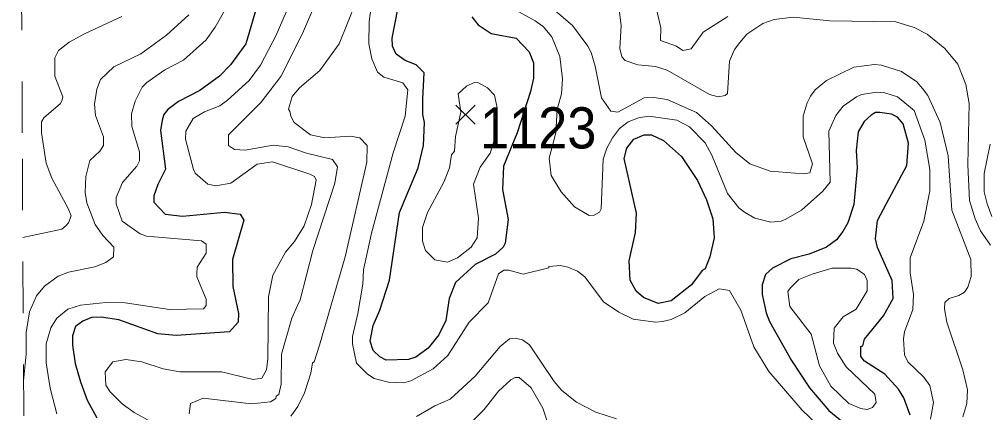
# Model space of a CAD drawing. Extents: x 423 to 448.8, y 7456.3 to 7484.
# Drawn here: x 423.019 to 424.902, y 7477.17 to 7477.935 of the extents above; entities that cross this region are included whole.
import ezdxf
from ezdxf.enums import TextEntityAlignment as Align

# ---------------------------------------------------------------- set-up
doc = ezdxf.new("R2010")
doc.units = 0
doc.header["$LTSCALE"] = 0.032
doc.linetypes.add('SHORT_DASHED', pattern=[2.7, 1.5, -1.2])
for name, color, linetype, lineweight in [('1', 7, 'Continuous', 25), ('2', 7, 'Continuous', 13), ('21', 7, 'Continuous', 25), ('22', 7, 'SHORT_DASHED', 13)]:
    doc.layers.add(name, color=color, linetype=linetype, lineweight=lineweight)
doc.layers.add('61', color=7, linetype='Continuous')

msp = doc.modelspace()

# ---------------------------------------------------------------- linework, layer by layer
at = {"layer": '1'}
for points in [[(423.4827, 7477.9691), (423.4587, 7477.8872), (423.4293, 7477.8461), (423.4076, 7477.8245), (423.3698, 7477.7966), (423.328, 7477.775), (423.3078, 7477.7595), (423.2994, 7477.7495), (423.2963, 7477.7387), (423.2932, 7477.7185), (423.3032, 7477.6435), (423.2878, 7477.6134), (423.28, 7477.5917), (423.28, 7477.5793), (423.3025, 7477.5561), (423.3357, 7477.5522), (423.4177, 7477.5599), (423.4479, 7477.5561), (423.4548, 7477.5445), (423.4332, 7477.4679), (423.4339, 7477.4153), (423.4448, 7477.3628), (423.444, 7477.3457), (423.427, 7477.3271), (423.3234, 7477.3202), (423.2878, 7477.3233), (423.212, 7477.3504), (423.1779, 7477.3558), (423.1594, 7477.355), (423.1424, 7477.348), (423.1284, 7477.3372), (423.1222, 7477.3194), (423.1222, 7477.3009), (423.1277, 7477.2653), (423.1377, 7477.2297), (423.1509, 7477.1941), (423.1694, 7477.1601)], [(423.898, 7477.9398), (423.9104, 7477.9243), (423.9359, 7477.9073), (423.9839, 7477.898), (424.0094, 7477.8717), (424.0179, 7477.85), (424.0179, 7477.8206), (424.0117, 7477.7943), (423.9863, 7477.7139), (423.9594, 7477.6494), (423.9576, 7477.6041), (423.9684, 7477.5453), (423.963, 7477.4996), (423.9591, 7477.4919), (423.9437, 7477.478), (423.9042, 7477.4579), (423.8663, 7477.423), (423.8539, 7477.3921), (423.8478, 7477.3488), (423.8338, 7477.321), (423.8129, 7477.2954), (423.789, 7477.2777), (423.7751, 7477.273), (423.7317, 7477.2722), (423.7193, 7477.2784), (423.7062, 7477.2908), (423.7008, 7477.3086), (423.7062, 7477.3395), (423.7194, 7477.3689), (423.7379, 7477.4277), (423.7572, 7477.5592), (423.7936, 7477.6458), (423.8044, 7477.6892), (423.806, 7477.734), (423.8029, 7477.7495), (423.8029, 7477.7804), (423.8052, 7477.8307), (423.7897, 7477.8461), (423.7688, 7477.8547), (423.751, 7477.867), (423.7441, 7477.8825), (423.7433, 7477.898), (423.7545, 7477.9544)], [(424.7496, 7477.1647), (424.7372, 7477.1988), (424.7272, 7477.2158), (424.7001, 7477.2444), (424.6606, 7477.2699), (424.6537, 7477.2792), (424.6537, 7477.2985), (424.6575, 7477.3001), (424.6607, 7477.3125), (424.6978, 7477.3581), (424.7163, 7477.3921), (424.7148, 7477.4269), (424.6862, 7477.4911), (424.6823, 7477.5082), (424.6862, 7477.5437), (424.7039, 7477.5769), (424.7434, 7477.6505), (424.7465, 7477.6938), (424.7357, 7477.7317), (424.7249, 7477.7448), (424.7132, 7477.7502), (424.6908, 7477.7533), (424.6823, 7477.7533), (424.6738, 7477.7487), (424.6599, 7477.7363), (424.6483, 7477.7162), (424.6444, 7477.6799), (424.6467, 7477.6458), (424.6398, 7477.5747), (424.6282, 7477.5391), (424.6189, 7477.5221), (424.6065, 7477.5058), (424.5872, 7477.4919), (424.5532, 7477.478), (424.5176, 7477.4687), (424.482, 7477.4509), (424.4688, 7477.4385), (424.4619, 7477.4184), (424.4619, 7477.3999), (424.4696, 7477.3643), (424.4765, 7477.3473), (424.5191, 7477.2715), (424.5539, 7477.2181), (424.5918, 7477.174), (424.6305, 7477.1423)]]:
    msp.add_lwpolyline(points, dxfattribs=at)
msp.add_lwpolyline([(424.1942, 7477.6644), (424.1989, 7477.6845), (424.2128, 7477.7015), (424.2329, 7477.71), (424.2468, 7477.71), (424.2701, 7477.6992), (424.3056, 7477.6682), (424.3366, 7477.6211), (424.3536, 7477.584), (424.366, 7477.5468), (424.3691, 7477.5097), (424.3606, 7477.4726), (424.3513, 7477.4494), (424.3458, 7477.4463), (424.3249, 7477.4184), (424.2855, 7477.3875), (424.26, 7477.382), (424.2314, 7477.3937), (424.2174, 7477.4061), (424.2059, 7477.4277), (424.2035, 7477.4648), (424.2159, 7477.5205), (424.2182, 7477.5577)], close=True, dxfattribs=at)
at = {"layer": '2'}
for points in [[(423.2189, 7477.5421), (423.2073, 7477.5762), (423.2073, 7477.5886), (423.2197, 7477.6172), (423.2475, 7477.6489), (423.2522, 7477.6598), (423.2522, 7477.6768), (423.2375, 7477.7263), (423.2367, 7477.751), (423.2437, 7477.7758), (423.2576, 7477.8028), (423.2669, 7477.8121), (423.3017, 7477.8368), (423.338, 7477.8554), (423.3821, 7477.8949), (423.3992, 7477.9196), (423.4502, 7478.0093)], [(423.5948, 7477.9676), (423.5693, 7477.9073), (423.5267, 7477.8237), (423.4889, 7477.7734), (423.4254, 7477.71), (423.4254, 7477.6892), (423.437, 7477.6814), (423.4579, 7477.6806), (423.5121, 7477.6899), (423.5415, 7477.6868), (423.5771, 7477.6744), (423.6273, 7477.662), (423.6374, 7477.6481), (423.632, 7477.6164), (423.5894, 7477.485), (423.5646, 7477.389), (423.5592, 7477.3782), (423.5484, 7477.3535), (423.5283, 7477.2839), (423.5275, 7477.2251), (423.5229, 7477.205), (423.5182, 7477.2019), (423.5175, 7477.1972), (423.5066, 7477.191), (423.4703, 7477.1872), (423.376, 7477.198), (423.3512, 7477.1879), (423.3488, 7477.1678)], [(423.673, 7477.9676), (423.6405, 7477.8872), (423.6025, 7477.8353), (423.5631, 7477.8013)], [(424.5841, 7477.1323), (424.54, 7477.1748), (424.475, 7477.2498), (424.4456, 7477.2978), (424.4209, 7477.3689), (424.3985, 7477.4076), (424.3784, 7477.4107), (424.3505, 7477.396), (424.3118, 7477.3643), (424.2855, 7477.3511), (424.2685, 7477.3473), (424.2546, 7477.3457), (424.2113, 7477.3519), (424.1834, 7477.365), (424.154, 7477.3852), (424.1177, 7477.4339), (424.103, 7477.4447), (424.0844, 7477.4525), (424.0705, 7477.4563), (424.0473, 7477.454), (424.0473, 7477.4517), (423.9978, 7477.4393), (423.97, 7477.447), (423.9599, 7477.447), (423.9499, 7477.44), (423.9297, 7477.3836), (423.8926, 7477.3457), (423.8516, 7477.2808), (423.823, 7477.2552), (423.7797, 7477.232), (423.7658, 7477.2281), (423.7364, 7477.2289), (423.7085, 7477.2366), (423.6954, 7477.2444), (423.6737, 7477.266), (423.666, 7477.304), (423.666, 7477.3179), (423.6768, 7477.3628), (423.6861, 7477.42), (423.6876, 7477.4478), (423.7031, 7477.519), (423.7449, 7477.6752), (423.7688, 7477.7464), (423.7735, 7477.7974), (423.7642, 7477.8114), (423.7271, 7477.8221), (423.7147, 7477.8322), (423.7039, 7477.8578), (423.6977, 7477.8872), (423.6985, 7477.9305), (423.7046, 7477.9738)], [(423.9506, 7477.9707), (424.021, 7477.932), (424.0365, 7477.9211), (424.0535, 7477.901), (424.069, 7477.8624), (424.0744, 7477.8191), (424.0721, 7477.7897), (424.0635, 7477.7595), (424.0613, 7477.7141), (424.0485, 7477.665), (424.052, 7477.6311), (424.0713, 7477.5994), (424.0976, 7477.57)], [(424.8517, 7477.1617), (424.8594, 7477.1879), (424.861, 7477.2142), (424.8517, 7477.2529), (424.8207, 7477.3457), (424.8161, 7477.372), (424.8169, 7477.3844), (424.8254, 7477.3921), (424.844, 7477.3975), (424.8548, 7477.4045), (424.8617, 7477.4138), (424.8679, 7477.4347), (424.8672, 7477.4679), (424.8308, 7477.5639), (424.8231, 7477.669), (424.8076, 7477.734), (424.7836, 7477.7866), (424.7736, 7477.8005), (424.7628, 7477.8129), (424.7326, 7477.833), (424.6939, 7477.8454), (424.68, 7477.8469), (424.6398, 7477.8415), (424.5872, 7477.816), (424.5647, 7477.7974), (424.5562, 7477.7851), (424.5493, 7477.7727), (424.5415, 7477.7464), (424.5415, 7477.7062), (424.5601, 7477.6536), (424.5547, 7477.6365), (424.5423, 7477.6342), (424.4774, 7477.6396), (424.4379, 7477.6536), (424.4108, 7477.676), (424.3636, 7477.7278), (424.3342, 7477.7533), (424.2778, 7477.7788), (424.2515, 7477.7827), (424.2329, 7477.782), (424.1819, 7477.7541), (424.1679, 7477.7564), (424.1502, 7477.7819), (424.1378, 7477.8438), (424.13, 7477.8701), (424.1231, 7477.8825), (424.0937, 7477.9227), (424.0403, 7477.9683)], [(423.5376, 7477.949), (423.5182, 7477.9042), (423.4873, 7477.8454), (423.4656, 7477.816), (423.4231, 7477.7773), (423.4084, 7477.7665), (423.379, 7477.7549), (423.3566, 7477.7417), (423.3427, 7477.717), (423.3419, 7477.7015), (423.3573, 7477.6427), (423.3605, 7477.6358), (423.3852, 7477.6141), (423.4007, 7477.611), (423.4301, 7477.6164), (423.4811, 7477.6528), (423.5105, 7477.6574), (423.5832, 7477.6334), (423.5925, 7477.6288)], [(424.5934, 7477.932), (424.5222, 7477.939), (424.4851, 7477.9343), (424.4634, 7477.9266), (424.4325, 7477.9057), (424.4185, 7477.8894), (424.4085, 7477.8763), (424.3985, 7477.8531), (424.3946, 7477.7904), (424.3899, 7477.7866), (424.3768, 7477.7843), (424.3598, 7477.7889), (424.2778, 7477.8361), (424.2546, 7477.843), (424.2206, 7477.8461), (424.1958, 7477.8546), (424.1896, 7477.8616), (424.1857, 7477.8779), (424.1881, 7477.9227), (424.1834, 7477.9583)], [(424.3954, 7477.9405), (424.3474, 7477.9096), (424.3242, 7477.8771), (424.308, 7477.874), (424.2956, 7477.8825), (424.2646, 7477.8933), (424.2654, 7477.9181), (424.2546, 7477.963)], [(423.0258, 7477.5106), (423.1013, 7477.5267), (423.1101, 7477.5336), (423.1145, 7477.5392), (423.1197, 7477.5529), (423.1137, 7477.5669), (423.082, 7477.6257), (423.0712, 7477.6551), (423.0619, 7477.7139), (423.0619, 7477.7355), (423.0665, 7477.7433), (423.099, 7477.7711), (423.1022, 7477.7781), (423.1037, 7477.7843), (423.0882, 7477.8245), (423.0882, 7477.8601), (423.0952, 7477.874), (423.1161, 7477.8902), (423.1455, 7477.9065), (423.2182, 7477.9405)], [(423.0272, 7477.2318), (423.0325, 7477.2839), (423.0325, 7477.3256), (423.0387, 7477.3658), (423.0526, 7477.3968), (423.0681, 7477.4161), (423.0944, 7477.4354), (423.1145, 7477.4432), (423.1656, 7477.4532), (423.1872, 7477.4617), (423.2019, 7477.4726), (423.2027, 7477.4919), (423.181, 7477.5143), (423.1663, 7477.536), (423.1501, 7477.5778), (423.147, 7477.5979), (423.1485, 7477.6288), (423.1562, 7477.6605), (423.1756, 7477.6783), (423.1826, 7477.6892), (423.1826, 7477.7062), (423.1671, 7477.7479), (423.1648, 7477.7696), (423.1694, 7477.799), (423.1764, 7477.8175), (423.2027, 7477.8423), (423.2553, 7477.8678), (423.3048, 7477.9041), (423.3481, 7477.9436)], [(424.9059, 7477.4957), (424.8865, 7477.5236), (424.8757, 7477.5468), (424.8648, 7477.5824), (424.8617, 7477.652), (424.864, 7477.7711), (424.8579, 7477.8083), (424.8424, 7477.8477), (424.8169, 7477.8778), (424.7829, 7477.9057), (424.7574, 7477.9188), (424.7218, 7477.9297), (424.5934, 7477.932)], [(423.5631, 7477.8013), (423.5492, 7477.785), (423.5422, 7477.7603), (423.5446, 7477.7564), (423.5461, 7477.7464), (423.5531, 7477.734), (423.5847, 7477.71), (423.6126, 7477.7046), (423.6621, 7477.7077), (423.6807, 7477.7046), (423.6946, 7477.6891), (423.6938, 7477.6567), (423.652, 7477.4726), (423.6018, 7477.3009), (423.5917, 7477.2684), (423.5886, 7477.2668), (423.5855, 7477.2467), (423.5732, 7477.2081), (423.56, 7477.1818), (423.5461, 7477.1632)], [(424.0976, 7477.57), (424.1262, 7477.553), (424.1355, 7477.5538), (424.1463, 7477.56), (424.1494, 7477.5661), (424.1532, 7477.6629), (424.1602, 7477.6845), (424.171, 7477.7046), (424.185, 7477.7224), (424.202, 7477.7355), (424.2221, 7477.7433), (424.2422, 7477.7463), (424.2964, 7477.7386), (424.3211, 7477.7255), (424.3513, 7477.6945), (424.3644, 7477.6706), (424.3946, 7477.5963), (424.417, 7477.5685), (424.4278, 7477.56), (424.448, 7477.5483), (424.4789, 7477.5406), (424.499, 7477.5422), (424.5083, 7477.546), (424.5384, 7477.5638), (424.5802, 7477.6009), (424.5941, 7477.618), (424.5918, 7477.717), (424.605, 7477.7479), (424.6197, 7477.7657), (424.6452, 7477.7843), (424.6553, 7477.7889), (424.6846, 7477.7928)], [(424.6846, 7477.7928), (424.7001, 7477.792), (424.7249, 7477.7843), (424.7573, 7477.7572), (424.7782, 7477.7), (424.7875, 7477.6427), (424.7875, 7477.601), (424.7759, 7477.5422), (424.7496, 7477.471), (424.7496, 7477.4416), (424.7558, 7477.3999), (424.755, 7477.3705), (424.7387, 7477.3272), (424.7364, 7477.3132), (424.7387, 7477.2823), (424.7449, 7477.2684), (424.7759, 7477.239), (424.7875, 7477.2227), (424.7952, 7477.1895), (424.7891, 7477.157)], [(424.9081, 7477.5515), (424.8989, 7477.5762), (424.8935, 7477.5994), (424.8935, 7477.635), (424.9051, 7477.6922)], [(423.5925, 7477.6288), (423.5956, 7477.6218), (423.5863, 7477.5747), (423.5724, 7477.5329), (423.5538, 7477.5027), (423.536, 7477.4819), (423.5113, 7477.437), (423.5028, 7477.3952), (423.502, 7477.2746), (423.4989, 7477.2529), (423.4904, 7477.2367), (423.4734, 7477.2343), (423.4115, 7477.249), (423.3311, 7477.249), (423.2986, 7477.2552), (423.2568, 7477.2684), (423.2259, 7477.273), (423.2004, 7477.2684), (423.1857, 7477.249), (423.1872, 7477.2235), (423.1957, 7477.2104), (423.2189, 7477.1871), (423.2421, 7477.1701), (423.3079, 7477.1338)], [(423.0921, 7477.1678), (423.0789, 7477.2173), (423.0712, 7477.2668), (423.0712, 7477.304), (423.0805, 7477.3349), (423.0921, 7477.3535), (423.113, 7477.3712), (423.1377, 7477.379), (423.1872, 7477.3844), (423.2244, 7477.3836), (423.311, 7477.3705), (423.3767, 7477.372), (423.3821, 7477.3782), (423.3821, 7477.3906), (423.3636, 7477.4339), (423.3636, 7477.4401), (423.3643, 7477.4525), (423.3821, 7477.4803), (423.3821, 7477.4865), (423.3821, 7477.4973), (423.3728, 7477.5043), (423.2661, 7477.5128), (423.2537, 7477.5174), (423.2189, 7477.5421)], [(423.7905, 7477.1624), (423.8261, 7477.1833), (423.8562, 7477.1964), (423.9042, 7477.2405), (423.9529, 7477.2985), (423.9715, 7477.3132), (423.9823, 7477.3148), (423.9963, 7477.3117), (424.0102, 7477.3016), (424.0581, 7477.2305), (424.0728, 7477.2127), (424.1014, 7477.1902), (424.1386, 7477.1709), (424.1788, 7477.1578)], [(423.8594, 7477.1137), (423.922, 7477.1763), (423.9498, 7477.2119), (423.9738, 7477.2336), (423.9823, 7477.2382), (423.9901, 7477.2382), (424.0133, 7477.2181), (424.0357, 7477.1787), (424.0512, 7477.1323)]]:
    msp.add_lwpolyline(points, dxfattribs=at)
for points in [[(423.9142, 7477.6473), (423.9336, 7477.6744), (423.9442, 7477.7077), (423.9468, 7477.7662), (423.9421, 7477.7874), (423.9282, 7477.8013), (423.9112, 7477.8114), (423.9027, 7477.8121), (423.888, 7477.8051), (423.8717, 7477.7897), (423.8769, 7477.7544), (423.8661, 7477.7067), (423.8644, 7477.6781), (423.8586, 7477.6713), (423.8547, 7477.6458), (423.8439, 7477.618), (423.8121, 7477.5592), (423.8021, 7477.5298), (423.8021, 7477.5035), (423.8083, 7477.485), (423.8261, 7477.4671), (423.8508, 7477.4625), (423.8702, 7477.471), (423.8965, 7477.4919), (423.9081, 7477.5097), (423.9112, 7477.5484), (423.9011, 7477.6141)], [(424.5593, 7477.4393), (424.598, 7477.4509), (424.6351, 7477.4509), (424.646, 7477.4486), (424.6606, 7477.4385), (424.666, 7477.4269), (424.666, 7477.4068), (424.6444, 7477.3712), (424.6197, 7477.3565), (424.6019, 7477.3341), (424.6003, 7477.3047), (424.6081, 7477.2854), (424.6251, 7477.2591), (424.6807, 7477.2057), (424.6838, 7477.1895), (424.6761, 7477.1802), (424.6661, 7477.1763), (424.6537, 7477.1779), (424.6305, 7477.1879), (424.5957, 7477.2212), (424.5732, 7477.2607), (424.557, 7477.3225), (424.516, 7477.3766), (424.5121, 7477.4053), (424.5168, 7477.4123), (424.533, 7477.4285)]]:
    msp.add_lwpolyline(points, close=True, dxfattribs=at)
at = {"layer": '21'}
for p, q in [((423.8667, 7477.7681), (423.9042, 7477.7306)), ((423.9042, 7477.7681), (423.8667, 7477.7306))]:
    msp.add_line(p, q, dxfattribs=at)
at = {"layer": '22'}
msp.add_lwpolyline([(423.0275, 7477.1635), (423.0247, 7477.7139), (423.0219, 7478.2787), (423.0207, 7478.5119), (423.0203, 7478.5895), (423.0199, 7478.6662), (423.0191, 7478.8202)], dxfattribs=at)

# ---------------------------------------------------------------- texts
at = {"layer": '61', "width": 0.95}
msp.add_text('1123', height=0.08, dxfattribs=at).set_placement((424.027, 7477.6837), align=Align.CENTER)

doc.saveas('drawing.dxf')
